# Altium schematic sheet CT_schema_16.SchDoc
size 278 x 170 mm
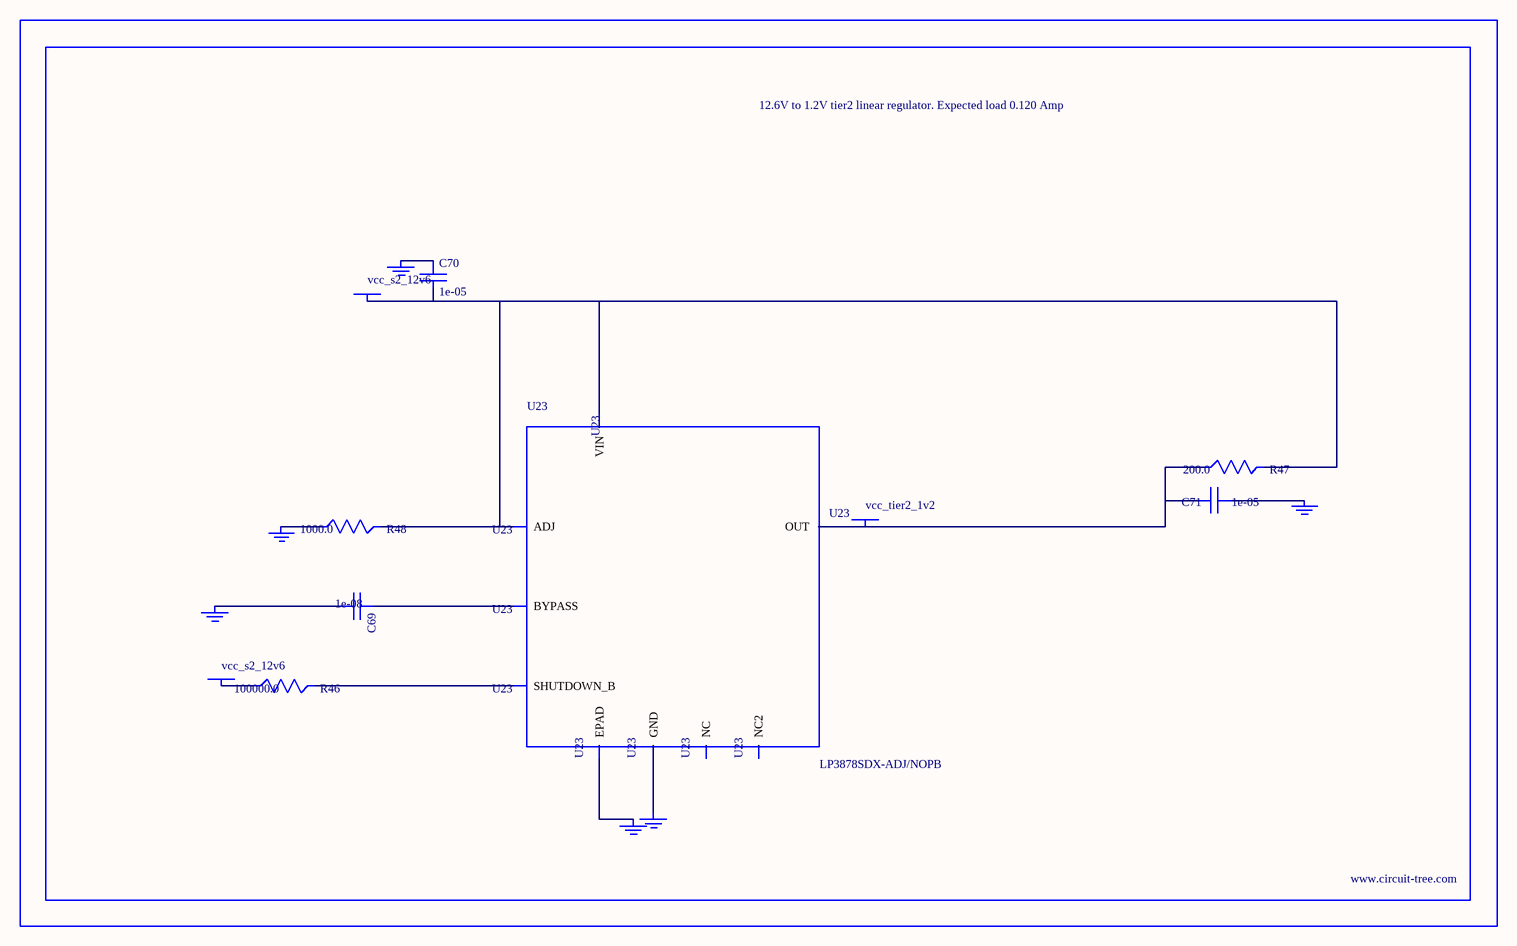
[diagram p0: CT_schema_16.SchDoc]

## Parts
BORDER15  (no value)
C69  1e-08  [C0402]
C70  1e-05  [C1210]
C71  1e-05  [C0805]
GND_INSTANCE_15_0  (no value)
GND_INSTANCE_15_1  (no value)
GND_INSTANCE_15_2  (no value)
GND_INSTANCE_15_3  (no value)
GND_INSTANCE_15_4  (no value)
GND_INSTANCE_15_5  (no value)
POWER_INSTANCE_15_0  vcc_s2_12v6
POWER_INSTANCE_15_1  vcc_s2_12v6
POWER_INSTANCE_15_2  vcc_tier2_1v2
R46  100000.0  [R0603]
R47  200.0  [R0603]
R48  1000.0  [R0603]
U23  LP3878SDX-ADJ/NOPB  [WSON-8]

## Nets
NetC69_1: C69.1 U23.1(BYPASS)
NetC69_2: C69.2 GND_INSTANCE_15_0.0(GND)
NetC70_1: C70.1 GND_INSTANCE_15_1.0(GND)
NetC70_2: C70.2 POWER_INSTANCE_15_0.0(PWR) R47.2 R48.2 U23.4(VIN) U23.6(ADJ)
NetC71_1: C71.1 GND_INSTANCE_15_2.0(GND)
NetC71_2: C71.2 POWER_INSTANCE_15_2.0(PWR) R47.1 U23.5(OUT)
NetGND_INSTANCE_15_3_0: GND_INSTANCE_15_3.0(GND) R48.1
NetGND_INSTANCE_15_4_0: GND_INSTANCE_15_4.0(GND) U23.PAD(EPAD)
NetGND_INSTANCE_15_5_0: GND_INSTANCE_15_5.0(GND) U23.3(GND)
NetPOWER_INSTANCE_15_1_0: POWER_INSTANCE_15_1.0(PWR) R46.1
NetR46_2: R46.2 U23.8(SHUTDOWN_B)

Not connected (* = marked no-connect by the designer): U23 2(NC) 7(NC2)

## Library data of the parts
BORDER15 = BORDER_PAGE15
C69 = C0402C103K3RAC
C70 = C1210C106K5PACTU
C71 = GRM219R60J106ME19D
GND_INSTANCE_15_0-GND_INSTANCE_15_5 = GND
POWER_INSTANCE_15_0-POWER_INSTANCE_15_2 = PWR
R46 = RC0603JR-07100KL
R47 = RC0603JR-07200RL
R48 = RC0603JR-071KL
